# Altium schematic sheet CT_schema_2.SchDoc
size 283 x 135 mm
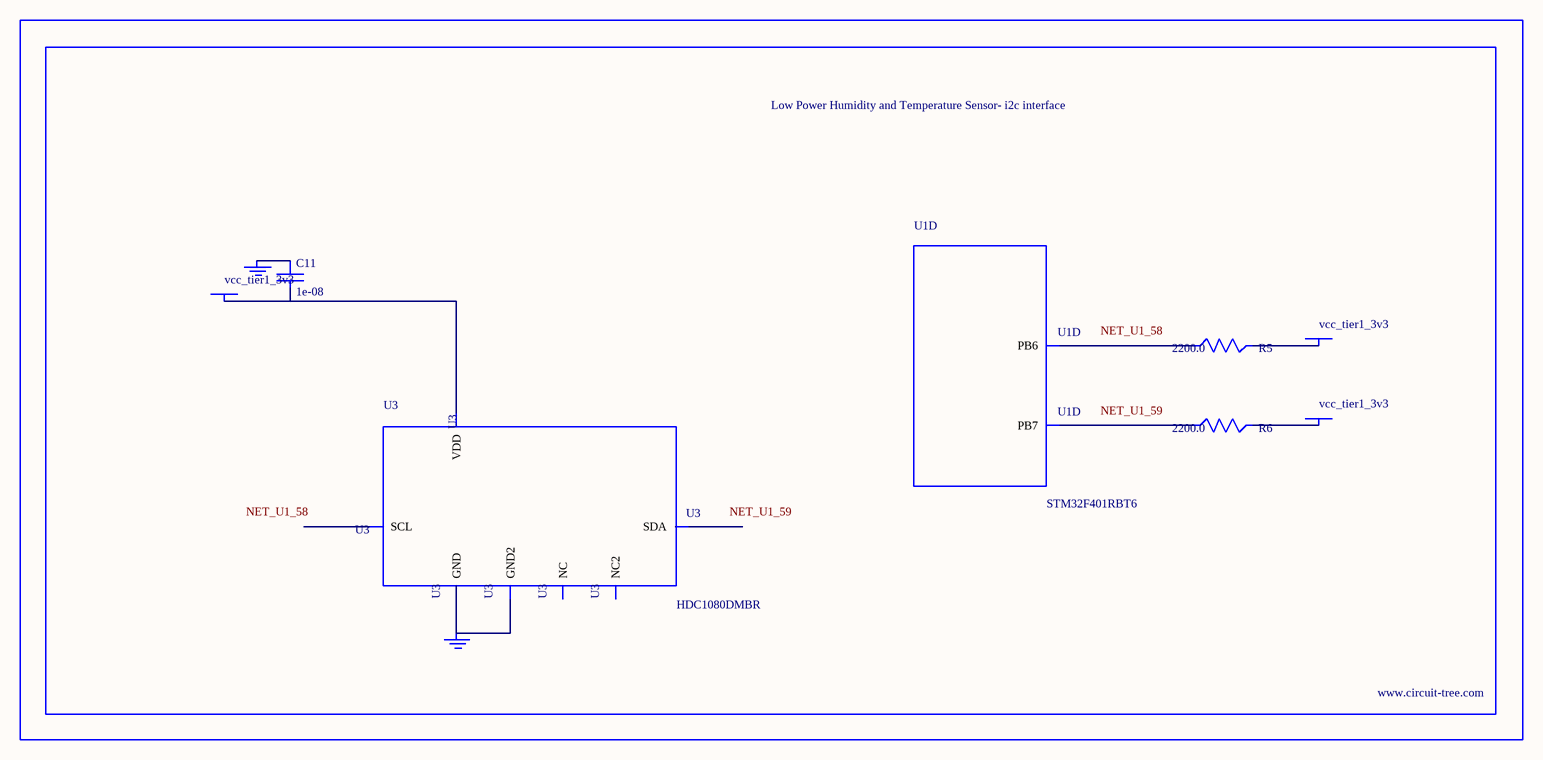
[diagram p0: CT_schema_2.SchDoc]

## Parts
BORDER1  (no value)
C11  1e-08  [C0402]
GND_INSTANCE_1_0  (no value)
GND_INSTANCE_1_1  (no value)
POWER_INSTANCE_1_0  vcc_tier1_3v3
POWER_INSTANCE_1_1  vcc_tier1_3v3
POWER_INSTANCE_1_2  vcc_tier1_3v3
R5  2200.0  [R0603]
R6  2200.0  [R0603]
U1  STM32F401RBT6  [LQFP64]  (part D of 7)
U3  HDC1080DMBR  [WSON-6]

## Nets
NetC11_1: C11.1 GND_INSTANCE_1_0.0(GND)
NetC11_2: C11.2 POWER_INSTANCE_1_0.0(PWR) U3.5(VDD)
NetGND_INSTANCE_1_1_0: GND_INSTANCE_1_1.0(GND) U3.2(GND) U3.PAD(GND2)
NetPOWER_INSTANCE_1_1_0: POWER_INSTANCE_1_1.0(PWR) R5.2
NetPOWER_INSTANCE_1_2_0: POWER_INSTANCE_1_2.0(PWR) R6.2
NetR5_1: R5.1 U1.58(PB6)
NetR6_1: R6.1 U1.59(PB7)

Not connected (* = marked no-connect by the designer): U3 1(SDA) 3(NC) 4(NC2) 6(SCL)

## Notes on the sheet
- Labels drawn without touching a wire or pin: NET_U1_58, NET_U1_59

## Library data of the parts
BORDER1 = BORDER_PAGE1
C11 = C0402C103K3RAC
GND_INSTANCE_1_0 GND_INSTANCE_1_1 = GND
POWER_INSTANCE_1_0-POWER_INSTANCE_1_2 = PWR
R5 R6 = RC0603JR-072K2L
